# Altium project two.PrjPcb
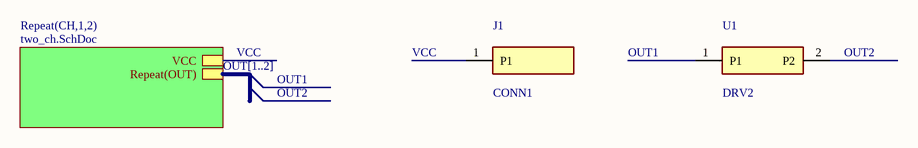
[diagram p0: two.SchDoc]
2 sheets, 6 parts. Net scope: hierarchical (ports join the sheet entries above them; power ports are global).
Sheets:
  two.SchDoc
    CH1 = two_ch.SchDoc
    CH2 = two_ch.SchDoc

## Sheet two.SchDoc
size A4

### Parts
J1  CONN1
U1  DRV2

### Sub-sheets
Repeat(CH,1,2) = two_ch.SchDoc: VCC, Repeat(OUT)

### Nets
OUT1: U1.1(P1)
OUT2: U1.2(P2)
VCC: J1.1(P1) ; sheet Repeat(CH,1,2)/VCC

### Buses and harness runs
bus OUT[1..2] = sheet Repeat(CH,1,2)/Repeat(OUT)

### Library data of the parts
J1 = CONN
U1 = DRIVER

## Sheet two_ch.SchDoc
size A4
Used 2 times, as channels CH1, CH2. Parts and nets are listed once, with the designators drawn on the sheet.
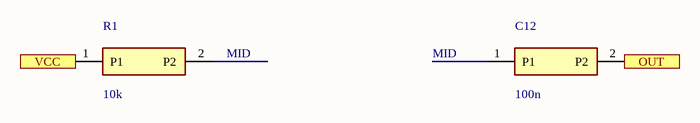
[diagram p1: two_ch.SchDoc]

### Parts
C12  100n
R1  10k

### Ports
OUT, VCC

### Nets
MID: C12.1(P1) R1.2(P2)
OUT: C12.2(P2) ; port OUT
VCC: R1.1(P1) ; port VCC

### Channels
CH1: designators end in _CH1; ports OUT=OUT1 VCC=VCC
CH2: designators end in _CH2; ports OUT=OUT2 VCC=VCC

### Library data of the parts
C12 = CAP
R1 = RES

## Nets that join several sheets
OUT1: two (U1.1), CH1 (C12_CH1.2)
OUT2: two (U1.2), CH2 (C12_CH2.2)
VCC: two (J1.1), CH1 (R1_CH1.1), CH2 (R1_CH2.1)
